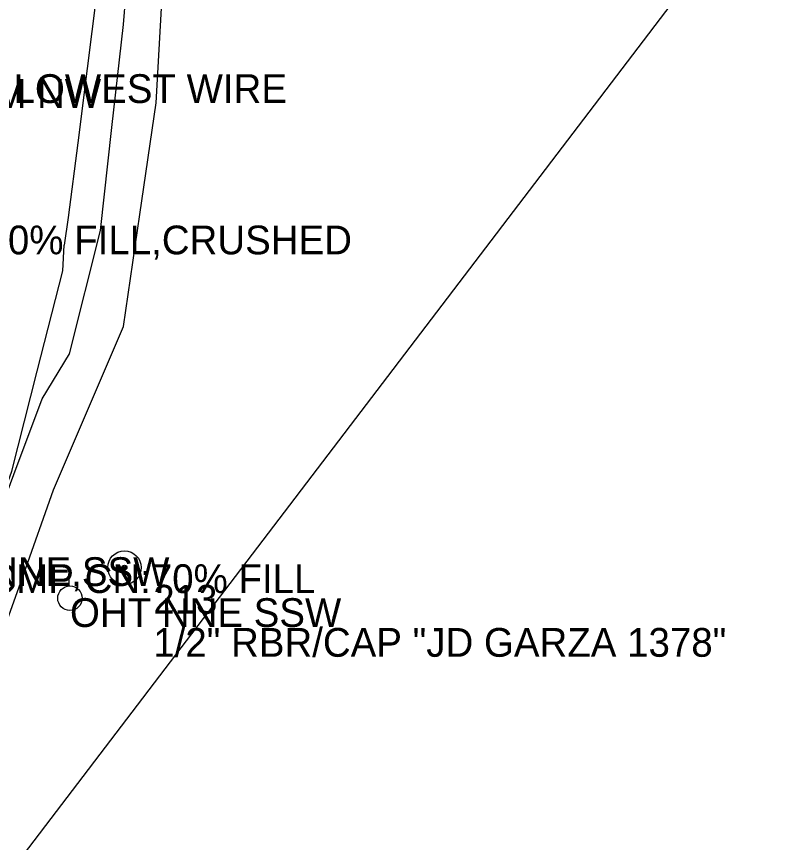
# Model space of a CAD drawing. Extents: x 997398 to 1003416, y 334596 to 337085.
# Drawn here: x 999603.2 to 999737.1, y 336342 to 336485.6 of the extents above; entities that cross this region are included whole.
import ezdxf

# ---------------------------------------------------------------- set-up
doc = ezdxf.new("R2010")
doc.units = 0
for name, color, linetype in [('Default', 7, 'Continuous'), ('S_DITCHLINE', 7, 'Continuous'), ('S_EDGE_PAVEMENT', 7, 'Continuous'), ('S_ELECTRIC_UTILITIES_ANNOT', 7, 'Continuous'), ('S_GAS_UTILITIES_ANNOT', 7, 'Continuous'), ('S_IRON_PIN', 7, 'Continuous'), ('S_IRON_PIN_ANNOT', 7, 'Continuous'), ('S_SHOULDER', 7, 'Continuous'), ('S_SIDE_DRAIN_ANNOT', 7, 'Continuous'), ('S_UTILITY_POLE', 7, 'Continuous'), ('S_UTILITY_POLE_ANNOT', 7, 'Continuous')]:
    doc.layers.add(name, color=color, linetype=linetype)

msp = doc.modelspace()

# ---------------------------------------------------------------- linework, layer by layer
at = {"layer": 'Default'}
msp.add_line((999557.02, 336277.74), (999737.12, 336514.03), dxfattribs=at)
at = {"layer": 'S_DITCHLINE'}
msp.add_lwpolyline([(999585.56, 336336.15), (999591.87, 336353.69), (999598.19, 336371.23), (999604.53, 336388.73), (999609.68, 336403.37), (999615.75, 336417.57), (999621.81, 336431.76), (999624.66, 336451.18), (999627.5, 336470.6), (999628.27, 336483.98), (999629.05, 336497.37), (999629.83, 336510.76), (999630.6, 336524.14), (999632.81, 336533.43), (999642.82, 336543.03), (999654.22, 336545.64), (999667.32, 336539.63), (999680.41, 336533.63)], dxfattribs=at)
at = {"layer": 'S_EDGE_PAVEMENT'}
for points in [[(999734.82, 336525.42), (999715.9, 336535.28), (999696.99, 336545.14), (999681.02, 336551.61), (999665.04, 336558.07), (999652.4, 336559.35), (999635.86, 336551.49), (999624.04, 336534.77), (999621.42, 336518.62), (999618.81, 336502.47), (999617.17, 336489.53), (999615.52, 336476.58), (999613.88, 336463.64), (999612.24, 336450.69), (999611.51, 336445.87)], [(999611.27, 336441.39), (999611.51, 336445.87)], [(999577.33, 336339.09), (999581.94, 336351.18), (999586.55, 336363.27), (999591.16, 336375.36), (999596.79, 336390.98), (999602.41, 336406.6), (999606.84, 336424), (999611.27, 336441.39)]]:
    msp.add_lwpolyline(points, dxfattribs=at)
at = {"layer": 'S_IRON_PIN'}
for radius in [2.91, 0.411, 0.262, 0.212, 0.145, 0.0822, 0.0581]:
    msp.add_circle((999622.01, 336389.83), radius, dxfattribs=at)
at = {"layer": 'S_SHOULDER'}
msp.add_lwpolyline([(999597.83, 336392.88), (999602.77, 336406.03), (999607.71, 336419.18), (999612.43, 336427.01), (999617.85, 336448.45), (999619.83, 336466.34), (999621.81, 336484.23), (999623.46, 336504.24), (999625.11, 336524.24), (999633.96, 336546.84), (999642.15, 336553.19), (999666.92, 336556.51), (999675.99, 336553.51), (999690.3, 336546.17), (999704.62, 336538.83), (999719.32, 336531.31), (999734.02, 336523.79)], dxfattribs=at)
at = {"layer": 'S_UTILITY_POLE'}
msp.add_line((999612.41, 336386.65), (999612.41, 336388.76), dxfattribs=at)
msp.add_circle((999612.53, 336384.51), 2.13, dxfattribs=at)

# ---------------------------------------------------------------- texts
at = {"layer": 'S_ELECTRIC_UTILITIES_ANNOT'}
msp.add_text('LOWEST WIRE', height=5, dxfattribs=at).set_placement((999602.72, 336470.59))
at = {"layer": 'S_GAS_UTILITIES_ANNOT'}
msp.add_text('FROM NW', height=5, dxfattribs=at).set_placement((999585.26, 336469.74))
at = {"layer": 'S_IRON_PIN_ANNOT'}
for s, p in [('213', (999627.01, 336381.83)), ('1/2" RBR/CAP "JD GARZA 1378"', (999627.01, 336374.33))]:
    msp.add_text(s, height=5, dxfattribs=at).set_placement(p)
at = {"layer": 'S_SIDE_DRAIN_ANNOT'}
for s, p in [('CN:100% FILL,CRUSHED', (999582.79, 336444.28)), ('DI:24 TY:CMP CN:70% FILL', (999570.12, 336385.41))]:
    msp.add_text(s, height=5, dxfattribs=at).set_placement(p)
at = {"layer": 'S_UTILITY_POLE_ANNOT'}
for s, p in [('W/LIGHT,OHE NNE,SSW', (999552.56, 336386.63)), ('OHT NNE SSW', (999612.53, 336379.51))]:
    msp.add_text(s, height=5, dxfattribs=at).set_placement(p)

doc.saveas('drawing.dxf')
